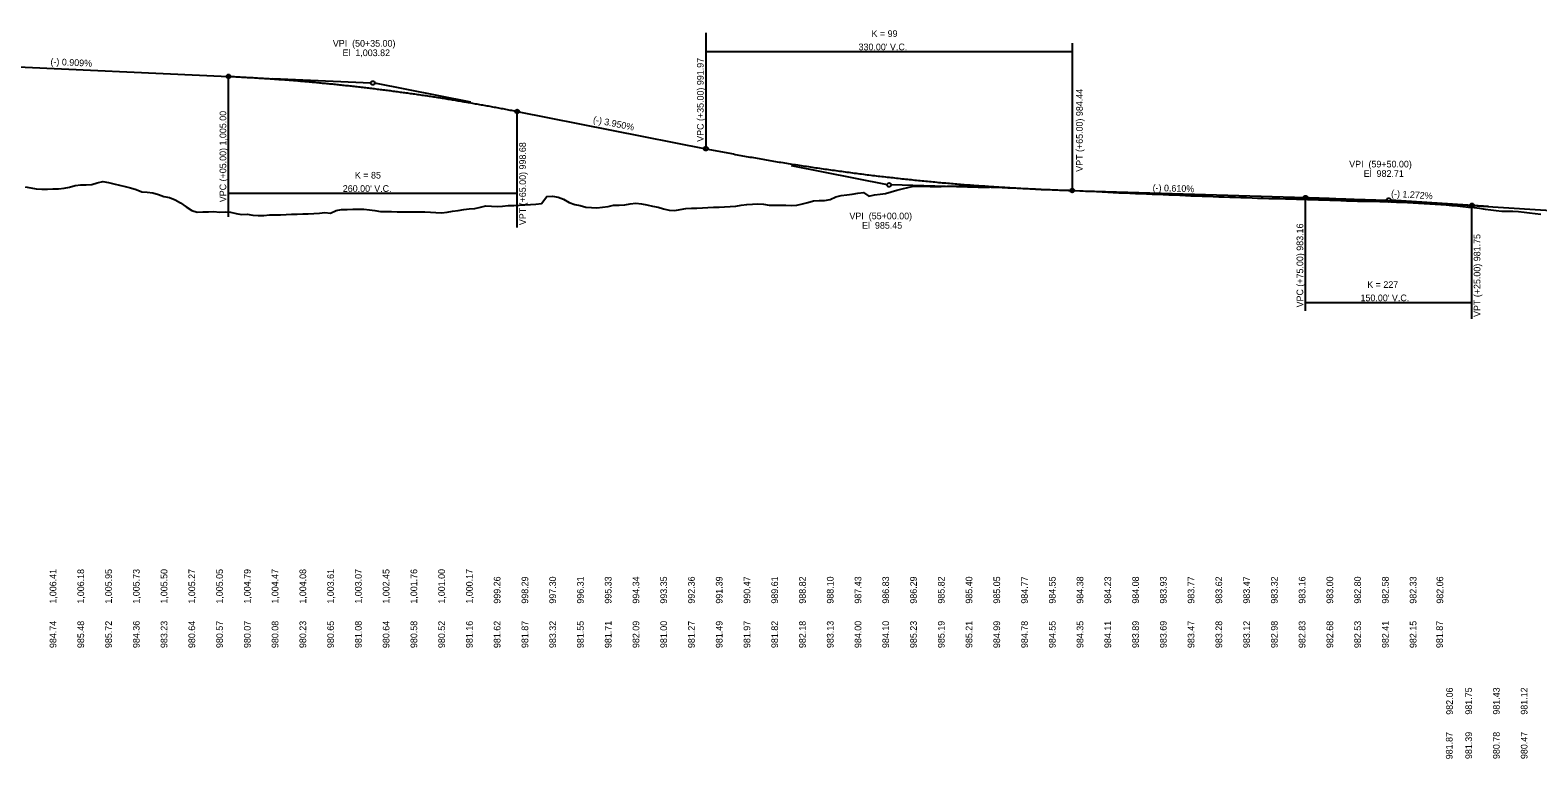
# Model space of a CAD drawing. Extents: x 126 to 16976848, y 7 to 12562190.
# Drawn here: x 16973908 to 16975266, y 12561517 to 12562174 of the extents above; entities that cross this region are included whole.
import ezdxf

# ---------------------------------------------------------------- set-up
doc = ezdxf.new("R2010")
doc.units = 0
for name, color, linetype in [('ANNOT_CONTOUR', 7, 'Continuous'), ('CLS_Shear_Line', 7, 'Continuous'), ('RD_EX_Conc-ZZ', 7, 'Continuous'), ('RD_HC_CL_50', 7, 'Continuous'), ('RD_HC_Points', 7, 'Continuous'), ('RD_PD_ConcMed', 7, 'Continuous'), ('RD_PD_SuperShp1', 7, 'Continuous')]:
    doc.layers.add(name, color=color, linetype=linetype)

msp = doc.modelspace()

# ---------------------------------------------------------------- linework, layer by layer
at = {"layer": 'CLS_Shear_Line'}
for p, q in [((16974516.5, 12562171.3), (16974516.5, 12562068.6)), ((16974516.5, 12562154.4), (16974846.5, 12562154.4)), ((16974846.5, 12562161.9), (16974846.5, 12562031)), ((16974086.5, 12562005.4), (16974086.5, 12562130.3)), ((16974346.5, 12561995.9), (16974346.5, 12562098.7)), ((16974086.5, 12562026.8), (16974346.5, 12562026.8)), ((16975056.5, 12561920.8), (16975056.5, 12562021.1)), ((16975206.5, 12561913.6), (16975206.5, 12562014)), ((16975056.5, 12561928.3), (16975206.5, 12561928.3))]:
    msp.add_line(p, q, dxfattribs=at)
for centre in [(16974086.5, 12562132), (16974346.5, 12562100.4), (16974516.5, 12562066.9), (16974846.5, 12562029.2), (16975056.5, 12562022.8), (16975206.5, 12562015.8)]:
    msp.add_circle(centre, 1.75, dxfattribs=at)
at = {"layer": 'RD_EX_Conc-ZZ'}
for p, q in [((16974126.6, 12562130.2), (16974214.8, 12562126.2)), ((16974304.8, 12562108.7), (16974218.2, 12562125.8)), ((16974593.2, 12562051.7), (16974679.8, 12562034.6)), ((16974771.5, 12562031.5), (16974683.3, 12562034.2)), ((16975041.5, 12562023.3), (16975129.8, 12562020.6)), ((16975221.3, 12562014.8), (16975133.3, 12562020.4))]:
    msp.add_line(p, q, dxfattribs=at)
for centre in [(16974216.5, 12562126.1), (16974681.5, 12562034.3), (16975131.5, 12562020.6)]:
    msp.add_circle(centre, 1.75, dxfattribs=at)
at = {"layer": 'RD_HC_Points'}
for points in [[(16973903.4, 12562032.6), (16973908.4, 12562031.7), (16973913.4, 12562030.8), (16973918.4, 12562030.4), (16973923.4, 12562030.5), (16973928.4, 12562030.6), (16973933.4, 12562030.8), (16973938.4, 12562031.2), (16973943.4, 12562032.2), (16973948.4, 12562033.7), (16973953.4, 12562034.4), (16973958.4, 12562034.4), (16973963.4, 12562034.7), (16973968.4, 12562036), (16973973.4, 12562037.2), (16973978.4, 12562036.4), (16973983.4, 12562035.2), (16973988.4, 12562034), (16973993.4, 12562032.9), (16973998.4, 12562031.6), (16974003.4, 12562030.1), (16974008.4, 12562028.1), (16974013.4, 12562027.6), (16974018.4, 12562027.1), (16974023.4, 12562025.5), (16974028.4, 12562023.7), (16974033.4, 12562022.9), (16974038.4, 12562020.9), (16974043.4, 12562018.1), (16974048.4, 12562014.6)], [(16974548.4, 12562016), (16974553.4, 12562016.7), (16974558.4, 12562017), (16974563.4, 12562017.1), (16974568.4, 12562016.9), (16974573.4, 12562016), (16974578.4, 12562016.1), (16974583.4, 12562016.1), (16974588.4, 12562015.9), (16974593.4, 12562015.6), (16974598.4, 12562016.1), (16974603.4, 12562017.1), (16974608.4, 12562018.5), (16974613.4, 12562019.8), (16974618.4, 12562020.3), (16974623.4, 12562020.1), (16974628.4, 12562021), (16974633.4, 12562023.6), (16974638.4, 12562024.6), (16974643.4, 12562025.3), (16974648.4, 12562026), (16974653.4, 12562026.7), (16974658.4, 12562027.3), (16974663.4, 12562024.1), (16974668.4, 12562025.2), (16974673.4, 12562025.8), (16974678.4, 12562026.6), (16974683.4, 12562028.1), (16974688.4, 12562029.4), (16974693.4, 12562030.7), (16974698.4, 12562031.9), (16974703.4, 12562033.1), (16974708.4, 12562033.2), (16974713.4, 12562033), (16974718.4, 12562032.8), (16974723.4, 12562032.9), (16974728.4, 12562032.9), (16974733.4, 12562033), (16974738.4, 12562033.1), (16974743.4, 12562033.1), (16974748.4, 12562033.2), (16974753.4, 12562033.2), (16974758.4, 12562033), (16974763.4, 12562032.7), (16974768.4, 12562032.5), (16974773.4, 12562032.3), (16974778.4, 12562032.1), (16974783.4, 12562031.9), (16974788.4, 12562031.7), (16974793.4, 12562031.5), (16974798.4, 12562031.3), (16974803.4, 12562031.1), (16974808.4, 12562030.8), (16974813.4, 12562030.6), (16974818.4, 12562030.4), (16974823.4, 12562030.1), (16974828.4, 12562029.9), (16974833.4, 12562029.7), (16974838.4, 12562029.5), (16974843.4, 12562029.4), (16974848.4, 12562029.2), (16974853.4, 12562028.9), (16974858.4, 12562028.7), (16974863.4, 12562028.5), (16974868.4, 12562028.2), (16974873.4, 12562028), (16974878.4, 12562027.7), (16974883.4, 12562027.5), (16974888.4, 12562027.2), (16974893.4, 12562027), (16974898.4, 12562026.8), (16974903.4, 12562026.6), (16974908.4, 12562026.4), (16974913.4, 12562026.2), (16974918.4, 12562025.9), (16974923.4, 12562025.8), (16974928.4, 12562025.6), (16974933.4, 12562025.4), (16974938.4, 12562025.2), (16974943.4, 12562025), (16974948.4, 12562024.8), (16974953.4, 12562024.5), (16974958.4, 12562024.3), (16974963.4, 12562024.1), (16974968.4, 12562024), (16974973.4, 12562023.8), (16974978.4, 12562023.6), (16974983.4, 12562023.4), (16974988.4, 12562023.2), (16974993.4, 12562023.1), (16974998.4, 12562023), (16975003.4, 12562022.8), (16975008.4, 12562022.6), (16975013.4, 12562022.4), (16975018.4, 12562022.2), (16975023.4, 12562022.1), (16975028.4, 12562022), (16975033.4, 12562021.9), (16975038.4, 12562021.8), (16975043.4, 12562021.6), (16975048.4, 12562021.5)], [(16974048.4, 12562014.6), (16974053.4, 12562011.2), (16974058.4, 12562009.7), (16974063.4, 12562009.9), (16974068.4, 12562010.1), (16974073.4, 12562010.3), (16974078.4, 12562009.8), (16974083.4, 12562009.9), (16974088.4, 12562009.6), (16974093.4, 12562008.6), (16974098.4, 12562007.7), (16974103.4, 12562007.9), (16974108.4, 12562007.1), (16974113.4, 12562006.6), (16974118.4, 12562006.7), (16974123.4, 12562007.3), (16974128.4, 12562007.4), (16974133.4, 12562007.4), (16974138.4, 12562007.6), (16974143.4, 12562007.8), (16974148.4, 12562007.9), (16974153.4, 12562008.1), (16974158.4, 12562008.3), (16974163.4, 12562008.4), (16974168.4, 12562008.7), (16974173.4, 12562009.3), (16974178.4, 12562008.7), (16974183.4, 12562011.3), (16974188.4, 12562012.2), (16974193.4, 12562012.2), (16974198.4, 12562012.3), (16974203.4, 12562012.4), (16974208.4, 12562012.4), (16974213.4, 12562011.9), (16974218.4, 12562011.3), (16974223.4, 12562010.4), (16974228.4, 12562010.3), (16974233.4, 12562010.2), (16974238.4, 12562010), (16974243.4, 12562009.9), (16974248.4, 12562009.9), (16974253.4, 12562009.9), (16974258.4, 12562009.9), (16974263.4, 12562010), (16974268.4, 12562009.7), (16974273.4, 12562009.3), (16974278.4, 12562009.2), (16974283.4, 12562009.8), (16974288.4, 12562010.7), (16974293.4, 12562011.1), (16974298.4, 12562012.1), (16974303.4, 12562012.6), (16974308.4, 12562013), (16974313.4, 12562014.2), (16974318.4, 12562015.3), (16974323.4, 12562015.1), (16974328.4, 12562014.9), (16974333.4, 12562015.2), (16974338.4, 12562015.7), (16974343.4, 12562015.6), (16974348.4, 12562015.9), (16974353.4, 12562016.2), (16974358.4, 12562016.5), (16974363.4, 12562016.9), (16974368.4, 12562017.6), (16974373.4, 12562023.9), (16974378.4, 12562024.2), (16974383.4, 12562023.3), (16974388.4, 12562021.3), (16974393.4, 12562018.4), (16974398.4, 12562016.5), (16974403.4, 12562015.7), (16974408.4, 12562014.2), (16974413.4, 12562014), (16974418.4, 12562013.5), (16974423.4, 12562014.1), (16974428.4, 12562014.9), (16974433.4, 12562015.9), (16974438.4, 12562016.1), (16974443.4, 12562016.4), (16974448.4, 12562017.2), (16974453.4, 12562017.7), (16974458.4, 12562017.3), (16974463.4, 12562016.2), (16974468.4, 12562015.2), (16974473.4, 12562014.1), (16974478.4, 12562012.8), (16974483.4, 12562011.6), (16974488.4, 12562011.1), (16974493.4, 12562012.1), (16974498.4, 12562013), (16974503.4, 12562013.4), (16974508.4, 12562013.4), (16974513.4, 12562013.6), (16974518.4, 12562014), (16974523.4, 12562014.2), (16974528.4, 12562014.3), (16974533.4, 12562014.5), (16974538.4, 12562014.8), (16974543.4, 12562015.2), (16974548.4, 12562016)], [(16975048.4, 12562021.5), (16975053.4, 12562021.3), (16975058.4, 12562021.1), (16975063.4, 12562021), (16975068.4, 12562020.9), (16975073.4, 12562020.7), (16975078.4, 12562020.5), (16975083.4, 12562020.4), (16975088.4, 12562020.2), (16975093.4, 12562020), (16975098.4, 12562019.8), (16975103.4, 12562019.7), (16975108.4, 12562019.6), (16975113.4, 12562019.6), (16975118.4, 12562019.5), (16975123.4, 12562019.3), (16975128.4, 12562019.2), (16975133.4, 12562019), (16975138.4, 12562018.8), (16975143.4, 12562018.6), (16975148.4, 12562018.3), (16975153.4, 12562018), (16975158.4, 12562017.7), (16975163.4, 12562017.4), (16975168.4, 12562017.1), (16975173.4, 12562016.8), (16975178.4, 12562016.6), (16975183.4, 12562016.3), (16975188.4, 12562015.8), (16975193.4, 12562015.3), (16975198.4, 12562014.8), (16975203.4, 12562014.3), (16975208.4, 12562013.8), (16975213.4, 12562013.2), (16975218.4, 12562012.5), (16975223.4, 12562011.9), (16975228.4, 12562011.3), (16975233.4, 12562010.7), (16975238.4, 12562010.5), (16975243.4, 12562010.7), (16975248.4, 12562010.4), (16975253.4, 12562009.8), (16975258.4, 12562009.1), (16975263.4, 12562008.5), (16975268.4, 12562007.8)]]:
    msp.add_lwpolyline(points, dxfattribs=at)
at = {"layer": 'RD_PD_ConcMed'}
for p, q in [((16973811.5, 12562144.5), (16974086.5, 12562132)), ((16974346.5, 12562100.4), (16974516.5, 12562066.9)), ((16974846.5, 12562029.2), (16975056.5, 12562022.8)), ((16975206.5, 12562015.8), (16975441.5, 12562000.8))]:
    msp.add_line(p, q, dxfattribs=at)
for points in [[(16974086.5, 12562132), (16974091.7, 12562131.8), (16974096.9, 12562131.5), (16974102.1, 12562131.2), (16974107.3, 12562131), (16974112.5, 12562130.6), (16974117.7, 12562130.3), (16974122.9, 12562130), (16974128.1, 12562129.6), (16974133.3, 12562129.3), (16974138.5, 12562128.9), (16974143.7, 12562128.5), (16974148.9, 12562128.1), (16974154.1, 12562127.6), (16974159.3, 12562127.2), (16974164.5, 12562126.7), (16974169.7, 12562126.2), (16974174.9, 12562125.7), (16974180.1, 12562125.2), (16974185.3, 12562124.7), (16974190.5, 12562124.1), (16974195.7, 12562123.6), (16974200.9, 12562123), (16974206.1, 12562122.4), (16974211.3, 12562121.8), (16974216.5, 12562121.2), (16974221.7, 12562120.5), (16974226.9, 12562119.9), (16974232.1, 12562119.2), (16974237.3, 12562118.5), (16974242.5, 12562117.8), (16974247.7, 12562117.1), (16974252.9, 12562116.4), (16974258.1, 12562115.6), (16974263.3, 12562114.9), (16974268.5, 12562114.1), (16974273.7, 12562113.3), (16974278.9, 12562112.5), (16974284.1, 12562111.6), (16974289.3, 12562110.8), (16974294.5, 12562109.9), (16974299.7, 12562109), (16974304.9, 12562108.2), (16974310.1, 12562107.2), (16974315.3, 12562106.3), (16974320.5, 12562105.4), (16974325.7, 12562104.4), (16974330.9, 12562103.5), (16974336.1, 12562102.5), (16974341.3, 12562101.5), (16974346.5, 12562100.4)], [(16974516.5, 12562066.9), (16974523.1, 12562065.6), (16974529.7, 12562064.3), (16974536.3, 12562063.1), (16974542.9, 12562061.8), (16974549.5, 12562060.6), (16974556.1, 12562059.4), (16974562.7, 12562058.3), (16974569.3, 12562057.1), (16974575.9, 12562056), (16974582.5, 12562054.9), (16974589.1, 12562053.9), (16974595.7, 12562052.8), (16974602.3, 12562051.8), (16974608.9, 12562050.8), (16974615.5, 12562049.8), (16974622.1, 12562048.8), (16974628.7, 12562047.9), (16974635.3, 12562047), (16974641.9, 12562046.1), (16974648.5, 12562045.2), (16974655.1, 12562044.4), (16974661.7, 12562043.5), (16974668.3, 12562042.7), (16974674.9, 12562041.9), (16974681.5, 12562041.2), (16974688.1, 12562040.4), (16974694.7, 12562039.7), (16974701.3, 12562039), (16974707.9, 12562038.3), (16974714.5, 12562037.7), (16974721.1, 12562037.1), (16974727.7, 12562036.4), (16974734.3, 12562035.9), (16974740.9, 12562035.3), (16974747.5, 12562034.7), (16974754.1, 12562034.2), (16974760.7, 12562033.7), (16974767.3, 12562033.3), (16974773.9, 12562032.8), (16974780.5, 12562032.4), (16974787.1, 12562032), (16974793.7, 12562031.6), (16974800.3, 12562031.2), (16974806.9, 12562030.9), (16974813.5, 12562030.5), (16974820.1, 12562030.2), (16974826.7, 12562030), (16974833.3, 12562029.7), (16974839.9, 12562029.5), (16974846.5, 12562029.2)], [(16975056.5, 12562022.8), (16975059.5, 12562022.8), (16975062.5, 12562022.7), (16975065.5, 12562022.6), (16975068.5, 12562022.5), (16975071.5, 12562022.4), (16975074.5, 12562022.3), (16975077.5, 12562022.2), (16975080.5, 12562022), (16975083.5, 12562021.9), (16975086.5, 12562021.8), (16975089.5, 12562021.7), (16975092.5, 12562021.6), (16975095.5, 12562021.5), (16975098.5, 12562021.4), (16975101.5, 12562021.2), (16975104.5, 12562021.1), (16975107.5, 12562021), (16975110.5, 12562020.9), (16975113.5, 12562020.7), (16975116.5, 12562020.6), (16975119.5, 12562020.5), (16975122.5, 12562020.3), (16975125.5, 12562020.2), (16975128.5, 12562020.1), (16975131.5, 12562019.9), (16975134.5, 12562019.8), (16975137.5, 12562019.6), (16975140.5, 12562019.5), (16975143.5, 12562019.4), (16975146.5, 12562019.2), (16975149.5, 12562019.1), (16975152.5, 12562018.9), (16975155.5, 12562018.7), (16975158.5, 12562018.6), (16975161.5, 12562018.4), (16975164.5, 12562018.3), (16975167.5, 12562018.1), (16975170.5, 12562017.9), (16975173.5, 12562017.8), (16975176.5, 12562017.6), (16975179.5, 12562017.4), (16975182.5, 12562017.2), (16975185.5, 12562017.1), (16975188.5, 12562016.9), (16975191.5, 12562016.7), (16975194.5, 12562016.5), (16975197.5, 12562016.4), (16975200.5, 12562016.2), (16975203.5, 12562016), (16975206.5, 12562015.8)]]:
    msp.add_spline(points, degree=3, dxfattribs=at)

# ---------------------------------------------------------------- texts
at = {"layer": 'ANNOT_CONTOUR'}
for s, p in [('984.74', (16973931.5, 12561617)), ('985.48', (16973956.5, 12561617)), ('985.72', (16973981.5, 12561617)), ('984.36', (16974006.5, 12561617)), ('983.23', (16974031.5, 12561617)), ('980.64', (16974056.5, 12561617)), ('980.57', (16974081.5, 12561617)), ('980.07', (16974106.5, 12561617)), ('980.08', (16974131.5, 12561617)), ('980.23', (16974156.5, 12561617)), ('980.65', (16974181.5, 12561617)), ('981.08', (16974206.5, 12561617)), ('980.64', (16974231.5, 12561617)), ('980.58', (16974256.5, 12561617)), ('980.52', (16974281.5, 12561617)), ('981.16', (16974306.5, 12561617)), ('981.62', (16974331.5, 12561617)), ('981.87', (16974356.5, 12561617)), ('983.32', (16974381.5, 12561617)), ('981.55', (16974406.5, 12561617)), ('981.71', (16974431.5, 12561617)), ('982.09', (16974456.5, 12561617)), ('981.00', (16974481.5, 12561617)), ('981.27', (16974506.5, 12561617)), ('981.49', (16974531.5, 12561617)), ('981.97', (16974556.5, 12561617)), ('981.82', (16974581.5, 12561617)), ('982.18', (16974606.5, 12561617)), ('983.13', (16974631.5, 12561617)), ('984.00', (16974656.5, 12561617)), ('984.10', (16974681.5, 12561617)), ('985.23', (16974706.5, 12561617)), ('985.19', (16974731.5, 12561617)), ('985.21', (16974756.5, 12561617)), ('984.99', (16974781.5, 12561617)), ('984.78', (16974806.5, 12561617)), ('984.55', (16974831.5, 12561617)), ('984.35', (16974856.5, 12561617)), ('984.11', (16974881.5, 12561617)), ('983.89', (16974906.5, 12561617)), ('983.69', (16974931.5, 12561617)), ('983.47', (16974956.5, 12561617)), ('983.28', (16974981.5, 12561617)), ('983.12', (16975006.5, 12561617)), ('982.98', (16975031.5, 12561617)), ('982.83', (16975056.5, 12561617)), ('982.68', (16975081.5, 12561617)), ('982.53', (16975106.5, 12561617)), ('982.41', (16975131.5, 12561617)), ('982.15', (16975156.5, 12561617)), ('981.87', (16975180.3, 12561617)), ('981.87', (16975189, 12561516.8)), ('981.39', (16975206.5, 12561517)), ('980.78', (16975231.5, 12561517)), ('980.47', (16975256.5, 12561517))]:
    msp.add_text(s, height=6, rotation=90, dxfattribs=at).set_placement(p)
at = {"layer": 'CLS_Shear_Line'}
for s, p in [('K = 99', (16974665.7, 12562167.6)), ("330.00' V.C.", (16974654, 12562155.6)), ('K = 85', (16974200.4, 12562040)), ("260.00' V.C.", (16974189.5, 12562028)), ('K = 227', (16975112.2, 12561941.5)), ("150.00' V.C.", (16975106.1, 12561929.5))]:
    msp.add_text(s, height=6, dxfattribs=at).set_placement(p)
for s, p in [('VPC (+35.00) 991.97', (16974514.5, 12562073.1)), ('VPT (+65.00) 984.44', (16974856, 12562046.1)), ('VPC (+05.00) 1,005.00', (16974084.5, 12562018.7)), ('VPT (+65.00) 998.68', (16974354.4, 12561998)), ('VPC (+75.00) 983.16', (16975054.5, 12561923.9)), ('VPT (+25.00) 981.75', (16975214.1, 12561915.3))]:
    msp.add_text(s, height=6, rotation=90, dxfattribs=at).set_placement(p)
at = {"layer": 'RD_EX_Conc-ZZ'}
for s, p in [('VPI  (50+35.00)', (16974180.5, 12562158.8)), ('El  1,003.82', (16974189.2, 12562150.3)), ('VPI  (59+50.00)', (16975095.9, 12562050)), ('El  982.71', (16975109, 12562041.5)), ('VPI  (55+00.00)', (16974645.8, 12562003.3)), ('El  985.45', (16974657.2, 12561994.8))]:
    msp.add_text(s, height=6, dxfattribs=at).set_placement(p)
at = {"layer": 'RD_HC_CL_50'}
for s, p in [('1,006.41', (16973931.5, 12561657)), ('1,006.18', (16973956.5, 12561657)), ('1,005.95', (16973981.5, 12561657)), ('1,005.73', (16974006.5, 12561657)), ('1,005.50', (16974031.5, 12561657)), ('1,005.27', (16974056.5, 12561657)), ('1,005.05', (16974081.5, 12561657)), ('1,004.79', (16974106.5, 12561657)), ('1,004.47', (16974131.5, 12561657)), ('1,004.08', (16974156.5, 12561657)), ('1,003.61', (16974181.5, 12561657)), ('1,003.07', (16974206.5, 12561657)), ('1,002.45', (16974231.5, 12561657)), ('1,001.76', (16974256.5, 12561657)), ('1,001.00', (16974281.5, 12561657)), ('1,000.17', (16974306.5, 12561657)), ('999.26', (16974331.5, 12561657)), ('998.29', (16974356.5, 12561657)), ('997.30', (16974381.5, 12561657)), ('996.31', (16974406.5, 12561657)), ('995.33', (16974431.5, 12561657)), ('994.34', (16974456.5, 12561657)), ('993.35', (16974481.5, 12561657)), ('992.36', (16974506.5, 12561657)), ('991.39', (16974531.5, 12561657)), ('990.47', (16974556.5, 12561657)), ('989.61', (16974581.5, 12561657)), ('988.82', (16974606.5, 12561657)), ('988.10', (16974631.5, 12561657)), ('987.43', (16974656.5, 12561657)), ('986.83', (16974681.5, 12561657)), ('986.29', (16974706.5, 12561657)), ('985.82', (16974731.5, 12561657)), ('985.40', (16974756.5, 12561657)), ('985.05', (16974781.5, 12561657)), ('984.77', (16974806.5, 12561657)), ('984.55', (16974831.5, 12561657)), ('984.38', (16974856.5, 12561657)), ('984.23', (16974881.5, 12561657)), ('984.08', (16974906.5, 12561657)), ('983.93', (16974931.5, 12561657)), ('983.77', (16974956.5, 12561657)), ('983.62', (16974981.5, 12561657)), ('983.47', (16975006.5, 12561657)), ('983.32', (16975031.5, 12561657)), ('983.16', (16975056.5, 12561657)), ('983.00', (16975081.5, 12561657)), ('982.80', (16975106.5, 12561657)), ('982.58', (16975131.5, 12561657)), ('982.33', (16975156.5, 12561657)), ('982.06', (16975180.6, 12561657)), ('982.06', (16975189.3, 12561556.9)), ('981.75', (16975206.5, 12561557)), ('981.43', (16975231.5, 12561557)), ('981.12', (16975256.5, 12561557))]:
    msp.add_text(s, height=6, rotation=90, dxfattribs=at).set_placement(p)
at = {"layer": 'RD_PD_SuperShp1'}
for s, rotation, p in [('(-) 0.909%', 357.3977, (16973926.1, 12562142.5)), ('(-) 3.950%', 348.8279, (16974414.5, 12562090.4)), ('(-) 0.610%', 358.253, (16974918.8, 12562028.8)), ('(-) 1.272%', 356.3618, (16975133.5, 12562023.7))]:
    msp.add_text(s, height=6, rotation=rotation, dxfattribs=at).set_placement(p)

doc.saveas('drawing.dxf')
